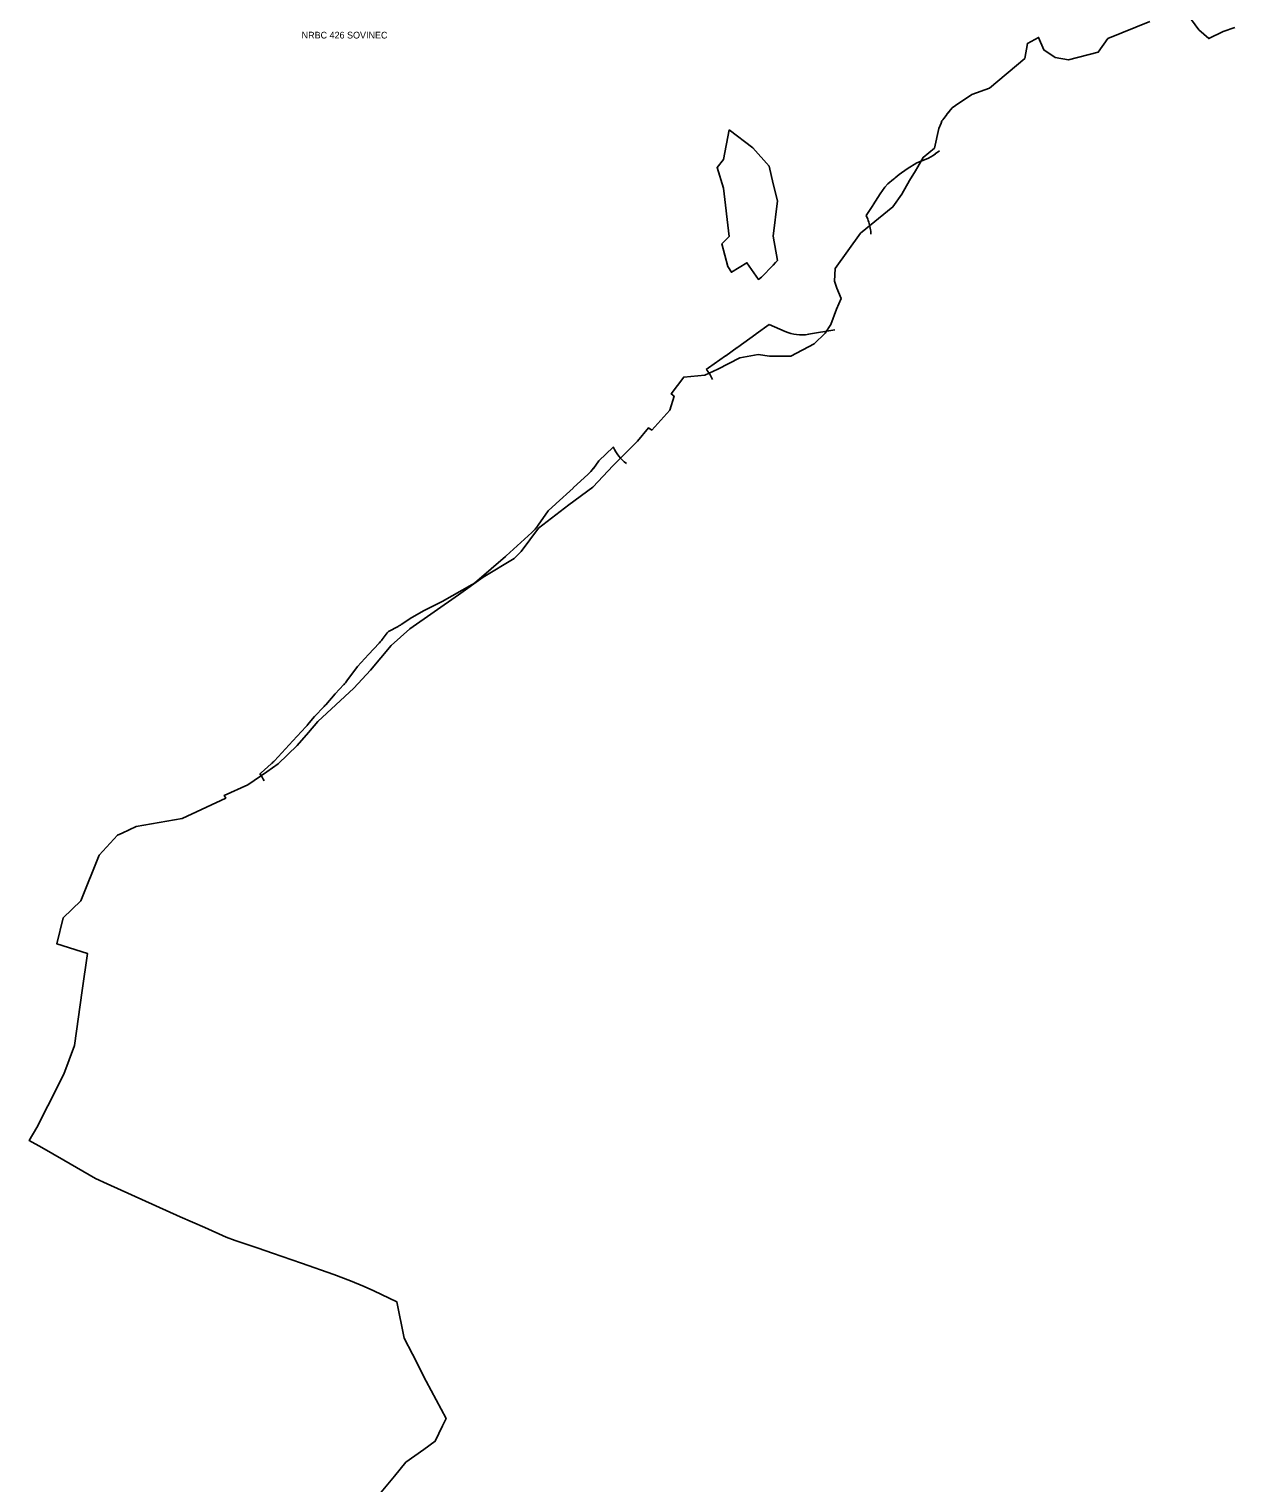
# Model space of a CAD drawing. Extents: x -547623 to -532764, y -1096714 to -1086523.
# Drawn here: x -544180 to -542743, y -1089946 to -1088213 of the extents above; entities that cross this region are included whole.
import ezdxf

# ---------------------------------------------------------------- set-up
doc = ezdxf.new("R2010")
doc.units = 0
for name, color, linetype in [('Vrstva 22', 7, 'Continuous'), ('Vrstva 23', 7, 'Continuous'), ('Vrstva 27', 7, 'Continuous'), ('Vrstva 36', 7, 'Continuous')]:
    doc.layers.add(name, color=color, linetype=linetype)

msp = doc.modelspace()

# ---------------------------------------------------------------- linework, layer by layer
at = {"layer": 'Vrstva 22'}
for points in [[(-543764.3, -1089961.5), (-543744.5, -1089937.8), (-543730.9, -1089921.2), (-543709.5, -1089905.8), (-543695.9, -1089896.1), (-543687.1, -1089877.8), (-543683, -1089869), (-543706.5, -1089824.6), (-543722.8, -1089792.5), (-543732.9, -1089773.2), (-543741.7, -1089729.8), (-543769, -1089716.9), (-543780.4, -1089711.7), (-543796.7, -1089705), (-543816.6, -1089697.5), (-543855, -1089683.9), (-543889.8, -1089671.9), (-543906.9, -1089665.9), (-543934.1, -1089656.9), (-543944.8, -1089653), (-543970.4, -1089641.2), (-543999.5, -1089628.7), (-544086.6, -1089589.2), (-544100.5, -1089582.9), (-544138.3, -1089561.2), (-544164.6, -1089546), (-544179.7, -1089537.5), (-544170.5, -1089522.2), (-544157.4, -1089496.5), (-544138.4, -1089458.4), (-544125.6, -1089424.6), (-544116.5, -1089359), (-544109.9, -1089314.8), (-544146.5, -1089303.3), (-544139.2, -1089272.4), (-544118.2, -1089252.1), (-544096.2, -1089197.5), (-544074.5, -1089173.9), (-544068.9, -1089171.2), (-544052.1, -1089163.3), (-543997.5, -1089153.8), (-543945.4, -1089129.6), (-543947.2, -1089126.3), (-543918.9, -1089113.9), (-543896.4, -1089098.1), (-543883, -1089088.6), (-543860.2, -1089066.7), (-543847, -1089051.5), (-543835.7, -1089038.3), (-543792.8, -1088998.5), (-543772.9, -1088977.2), (-543748.4, -1088947.7), (-543726.2, -1088927.7), (-543668.3, -1088887.2), (-543638.7, -1088866), (-543601.7, -1088843.9), (-543593.5, -1088835.6), (-543572.8, -1088807.6), (-543536.8, -1088780), (-543508.1, -1088759.1), (-543484, -1088733), (-543454.7, -1088704), (-543441.8, -1088688.3), (-543438, -1088690.9), (-543416.5, -1088667.2), (-543411.4, -1088650.5), (-543414.6, -1088647.7), (-543399.8, -1088627.7), (-543374.8, -1088625.5), (-543359.1, -1088618.2), (-543333.1, -1088604.8), (-543311.1, -1088600.6), (-543297.5, -1088602.6), (-543272.1, -1088602.6), (-543244.4, -1088588), (-543231.4, -1088575.3), (-543224.6, -1088564.9), (-543217.7, -1088546.6), (-543212.3, -1088533.9), (-543217.5, -1088521.9), (-543220.3, -1088513.3), (-543219.6, -1088498.4), (-543189.2, -1088456), (-543150.7, -1088424.8), (-543140, -1088409.8), (-543130.7, -1088393.5), (-543123.8, -1088381.8), (-543121.1, -1088377.2), (-543114.4, -1088365.8), (-543101, -1088354.8), (-543095.8, -1088331.4), (-543093.3, -1088325.1), (-543092.2, -1088322.4), (-543091.3, -1088321.2), (-543089.8, -1088319.3), (-543087.2, -1088315.9), (-543085.8, -1088314.1), (-543083.5, -1088311.2), (-543080.1, -1088306.8), (-543076, -1088303.9), (-543056.7, -1088290.7), (-543035.4, -1088283.4), (-542993.3, -1088247.8), (-542990.3, -1088230), (-542977, -1088222.9), (-542970.7, -1088237.8), (-542957.2, -1088246.8), (-542941.3, -1088249.5), (-542906.1, -1088240.5), (-542894.4, -1088224.2), (-542844.6, -1088203.7)], [(-542795.1, -1088201.7), (-542786.1, -1088213.7), (-542774.2, -1088224.2), (-542757.3, -1088215.6), (-542743.2, -1088210.9)]]:
    msp.add_lwpolyline(points, dxfattribs=at)
at = {"layer": 'Vrstva 23'}
for p, q in [((-543182.5, -1088434.9), (-543174.7, -1088423.2)), ((-543180.6, -1088439.4), (-543182.5, -1088434.9)), ((-543176.8, -1088457.2), (-543177.1, -1088453.9)), ((-543335.4, -1088592.2), (-543313.8, -1088576.5)), ((-543313.5, -1088576.3), (-543298.2, -1088565)), ((-543298.2, -1088565), (-543279.1, -1088573.3)), ((-543251, -1088576.7), (-543219.9, -1088571.4)), ((-543349.7, -1088602.3), (-543336, -1088592.6)), ((-543531.5, -1088759.8), (-543513.8, -1088743.6)), ((-543551.8, -1088778.4), (-543531.5, -1088759.9)), ((-543611.5, -1088840.7), (-543580.8, -1088812.9)), ((-543646.2, -1088870.8), (-543612.3, -1088841.4)), ((-543684.9, -1088893.5), (-543654.7, -1088876.7)), ((-543903.3, -1089099.4), (-543891.1, -1089088.7))]:
    msp.add_line(p, q, dxfattribs=at)
for points in [[(-543147.9, -1088390.3), (-543143.1, -1088386.1), (-543133.5, -1088379.3), (-543122, -1088372.4), (-543111.1, -1088367.9)], [(-543100.1, -1088361.6), (-543095.2, -1088357.9)], [(-543174.1, -1088422.2), (-543165.8, -1088409.1), (-543160.4, -1088401.5), (-543156.5, -1088397.2), (-543149.8, -1088391.8)], [(-543372.9, -1088618.5), (-543370.3, -1088616.6), (-543350, -1088602.5)], [(-543507.4, -1088736.5), (-543500.9, -1088727.7), (-543483.7, -1088711.1)], [(-543573.1, -1088804.1), (-543561.4, -1088787), (-543552.3, -1088778.8)], [(-543736.6, -1088922.7), (-543723.6, -1088914.1), (-543709.1, -1088906.1), (-543686.1, -1088894.2)], [(-543759.1, -1088940.5), (-543753.2, -1088932.7), (-543751.4, -1088931.1), (-543740, -1088924.8)], [(-543801, -1088989.7), (-543788.4, -1088972.7), (-543775.4, -1088958.2), (-543762.8, -1088945)], [(-543826.3, -1089018.2), (-543815.2, -1089005.2), (-543804.9, -1088994.3)], [(-543847.9, -1089042.2), (-543839.8, -1089032.4), (-543828.2, -1089020.3)], [(-543887.4, -1089085), (-543865.6, -1089061.1), (-543850, -1089044.6)]]:
    msp.add_lwpolyline(points, dxfattribs=at)
for centre, start, end in [((-543130.2, -1088321.7), 292.5456, 307.094), ((-543180.9, -1088352.7), 308.4506, 311.2159), ((-543216.4, -1088395.6), 326.5004, 327.8624), ((-543226.9, -1088458.4), 5.1319, 22.2621), ((-543343.2, -1088536), 305.9833, 306.3705), ((-543259.3, -1088527.4), 246.6213, 279.588), ((-543364.8, -1088551.8), 305.1848, 305.9833), ((-543378.5, -1088561.4), 304.8277, 305.1848), ((-543411.4, -1088650.5), 23.255, 39.742), ((-543438, -1088690.9), 203.7093, 233.0037), ((-543547.6, -1088706.7), 312.5544, 323.4961), ((-543565.3, -1088723), 312.4529, 312.5544), ((-543585.6, -1088741.6), 311.7845, 312.4529), ((-543614.4, -1088775.9), 312.1572, 325.5993), ((-543645, -1088803.6), 310.87, 312.1572), ((-543679, -1088833), 299.09, 310.87), ((-543709.2, -1088849.8), 297.5168, 299.09), ((-543764.3, -1088881.1), 299.0824, 303.7169), ((-543799.1, -1088910.5), 316.4231, 323.1301), ((-543841.1, -1088959.9), 316.437, 323.4047), ((-543864.4, -1088985.8), 316.2995, 319.5835), ((-543886.4, -1089010.3), 316.6096, 320.2803), ((-543924.3, -1089051.3), 311.6277, 317.6498), ((-543936.5, -1089062.1), 309.5953, 311.6277), ((-543945.4, -1089129.6), 24.2293, 35.3967)]:
    msp.add_arc(centre, 50, start, end, dxfattribs=at)
at = {"layer": 'Vrstva 27'}
for points in [[(-543764.3, -1089961.5), (-543744.5, -1089937.8), (-543730.9, -1089921.2), (-543709.5, -1089905.8), (-543695.9, -1089896.1), (-543687.1, -1089877.8), (-543683, -1089869), (-543706.5, -1089824.6), (-543722.8, -1089792.5), (-543732.9, -1089773.2), (-543741.7, -1089729.8), (-543769, -1089716.9), (-543780.4, -1089711.7), (-543796.7, -1089705), (-543816.6, -1089697.5), (-543855, -1089683.9), (-543889.8, -1089671.9), (-543906.9, -1089665.9), (-543934.1, -1089656.9), (-543944.8, -1089653), (-543970.4, -1089641.2), (-543999.5, -1089628.7), (-544086.6, -1089589.2), (-544100.5, -1089582.9), (-544138.3, -1089561.2), (-544164.6, -1089546), (-544179.7, -1089537.5), (-544170.5, -1089522.2), (-544157.4, -1089496.5), (-544138.4, -1089458.4), (-544125.6, -1089424.6), (-544116.5, -1089359), (-544109.9, -1089314.8), (-544146.5, -1089303.3), (-544139.2, -1089272.4), (-544118.2, -1089252.1), (-544096.2, -1089197.5), (-544074.5, -1089173.9), (-544068.9, -1089171.2), (-544052.1, -1089163.3), (-543997.5, -1089153.8), (-543945.4, -1089129.6), (-543947.2, -1089126.3), (-543918.9, -1089113.9), (-543896.4, -1089098.1), (-543883, -1089088.6), (-543860.2, -1089066.7), (-543847, -1089051.5), (-543835.7, -1089038.3), (-543792.8, -1088998.5), (-543772.9, -1088977.2), (-543748.4, -1088947.7), (-543726.2, -1088927.7), (-543668.3, -1088887.2), (-543638.7, -1088866), (-543601.7, -1088843.9), (-543593.5, -1088835.6), (-543572.8, -1088807.6), (-543536.8, -1088780), (-543508.1, -1088759.1), (-543484, -1088733), (-543454.7, -1088704), (-543441.8, -1088688.3), (-543438, -1088690.9), (-543416.5, -1088667.2), (-543411.4, -1088650.5), (-543414.6, -1088647.7), (-543399.8, -1088627.7), (-543374.8, -1088625.5), (-543359.1, -1088618.2), (-543333.1, -1088604.8), (-543311.1, -1088600.6), (-543297.5, -1088602.6), (-543272.1, -1088602.6), (-543244.4, -1088588), (-543231.4, -1088575.3), (-543224.6, -1088564.9), (-543217.7, -1088546.6), (-543212.3, -1088533.9), (-543217.5, -1088521.9), (-543220.3, -1088513.3), (-543219.6, -1088498.4), (-543189.2, -1088456), (-543150.7, -1088424.8), (-543140, -1088409.8), (-543130.7, -1088393.5), (-543123.8, -1088381.8), (-543121.1, -1088377.2), (-543114.4, -1088365.8), (-543101, -1088354.8), (-543095.8, -1088331.4), (-543093.3, -1088325.1), (-543092.7, -1088323.6), (-543092.2, -1088322.4), (-543091.3, -1088321.2), (-543089.8, -1088319.3), (-543087.2, -1088315.9), (-543085.8, -1088314.1), (-543084.3, -1088312.2), (-543083.5, -1088311.2), (-543080.1, -1088306.8), (-543076, -1088303.9), (-543056.7, -1088290.7), (-543035.4, -1088283.4), (-542993.3, -1088247.8), (-542990.3, -1088230), (-542977, -1088222.9), (-542970.7, -1088237.8), (-542957.2, -1088246.8), (-542941.3, -1088249.5), (-542906.1, -1088240.5), (-542894.4, -1088224.2), (-542844.6, -1088203.7)], [(-542795.1, -1088201.7), (-542786.1, -1088213.7), (-542774.2, -1088224.2), (-542757.3, -1088215.6), (-542743.2, -1088210.9)], [(-543345.5, -1088332.9), (-543317.4, -1088354.3), (-543298, -1088376.1), (-543293.2, -1088397.4), (-543288.1, -1088417.7), (-543293.4, -1088459.7), (-543288.1, -1088488.7), (-543290.6, -1088491.2), (-543293.4, -1088494.1), (-543307, -1088508.4), (-543310.9, -1088511.3), (-543324.5, -1088491.5), (-543343.1, -1088502.8), (-543347.3, -1088496), (-543354.5, -1088468.8), (-543345.6, -1088460), (-543352.4, -1088402.4), (-543360, -1088377.9), (-543352.5, -1088368.3), (-543345.5, -1088332.9)]]:
    msp.add_lwpolyline(points, dxfattribs=at)

# ---------------------------------------------------------------- texts
at = {"layer": 'Vrstva 36'}
msp.add_text('NRBC 426 SOVINEC', height=8, dxfattribs=at).set_placement((-543855, -1088224.1))

doc.saveas('drawing.dxf')
